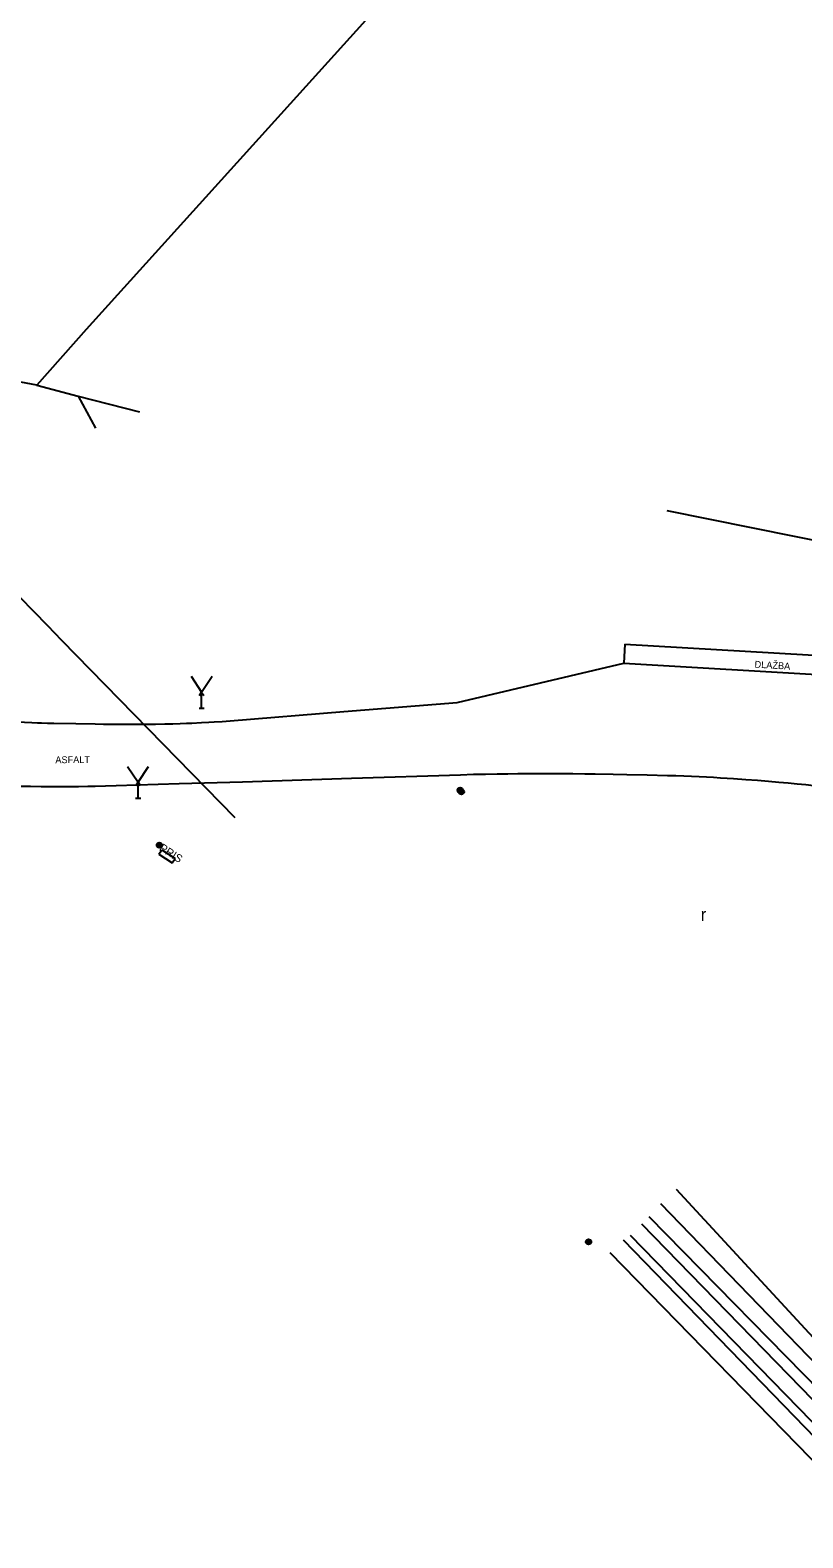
# Model space of a CAD drawing. Extents: x -540235 to -537963, y -1184915 to -1183660.
# Drawn here: x -538311.8 to -538238.6, y -1183987.5 to -1183844.8 of the extents above; entities that cross this region are included whole.
import ezdxf

# ---------------------------------------------------------------- set-up
doc = ezdxf.new("R2010")
doc.units = 0
for name, color, linetype in [('Vrstva 10', 7, 'Continuous'), ('Vrstva 11', 7, 'Continuous'), ('Vrstva 12', 7, 'Continuous'), ('Vrstva 13', 7, 'Continuous'), ('Vrstva 14', 7, 'Continuous'), ('Vrstva 24', 7, 'Continuous'), ('Vrstva 25', 7, 'Continuous'), ('Vrstva 36', 7, 'Continuous'), ('Vrstva 40', 7, 'Continuous'), ('Vrstva 41', 7, 'Continuous'), ('Vrstva 7', 7, 'Continuous')]:
    doc.layers.add(name, color=color, linetype=linetype)

msp = doc.modelspace()

# ---------------------------------------------------------------- linework, layer by layer
at = {"layer": 'Vrstva 10'}
for p, q in [((-538271.38, -1183908.42), (-538255.61, -1183904.7)), ((-538255.61, -1183904.7), (-538235.7, -1183905.88)), ((-538282.12, -1183909.285), (-538271.38, -1183908.42)), ((-538292.86, -1183910.15), (-538282.12, -1183909.285)), ((-538291.71, -1183915.91), (-538281.38, -1183915.58)), ((-538281.38, -1183915.58), (-538271.05, -1183915.25)), ((-538306.337, -1183916.342), (-538305.668, -1183916.331)), ((-538303.66, -1183916.28), (-538297.685, -1183916.096)), ((-538297.685, -1183916.096), (-538291.71, -1183915.91))]:
    msp.add_line(p, q, dxfattribs=at)
for points in [[(-538318.057, -1183909.725), (-538317.529, -1183909.794), (-538317.034, -1183909.855), (-538316.569, -1183909.909), (-538316.134, -1183909.958), (-538315.725, -1183910.001), (-538314.958, -1183910.076), (-538314.287, -1183910.135), (-538313.699, -1183910.182), (-538313.184, -1183910.219), (-538312.733, -1183910.249), (-538312.339, -1183910.273), (-538311.647, -1183910.309), (-538311.129, -1183910.332), (-538310.739, -1183910.347), (-538310.155, -1183910.366), (-538309.57, -1183910.38)], [(-538309.57, -1183910.38), (-538307.481, -1183910.421), (-538305.652, -1183910.45), (-538304.852, -1183910.461), (-538304.102, -1183910.469), (-538303.398, -1183910.474), (-538302.739, -1183910.477), (-538302.12, -1183910.477), (-538300.961, -1183910.473), (-538299.947, -1183910.463)], [(-538299.947, -1183910.463), (-538299.06, -1183910.448), (-538298.284, -1183910.43), (-538297.605, -1183910.41)], [(-538297.605, -1183910.41), (-538297.011, -1183910.39), (-538296.492, -1183910.369), (-538295.583, -1183910.327), (-538294.902, -1183910.29), (-538294.391, -1183910.26), (-538293.625, -1183910.208), (-538292.86, -1183910.15)], [(-538271.05, -1183915.25), (-538269.826, -1183915.215), (-538268.679, -1183915.188), (-538267.603, -1183915.169), (-538266.594, -1183915.155), (-538265.648, -1183915.146), (-538264.762, -1183915.14)], [(-538264.762, -1183915.14), (-538263.93, -1183915.137), (-538263.151, -1183915.137), (-538261.689, -1183915.142), (-538260.411, -1183915.151), (-538259.292, -1183915.163), (-538258.313, -1183915.176), (-538256.599, -1183915.204), (-538255.314, -1183915.229)], [(-538255.314, -1183915.229), (-538253.387, -1183915.272), (-538251.46, -1183915.32), (-538250.674, -1183915.342), (-538249.913, -1183915.368), (-538249.177, -1183915.397), (-538248.463, -1183915.428), (-538247.772, -1183915.461), (-538247.103, -1183915.496), (-538246.454, -1183915.533), (-538245.827, -1183915.571)], [(-538245.827, -1183915.571), (-538245.219, -1183915.61), (-538244.041, -1183915.692)], [(-538244.041, -1183915.692), (-538242.938, -1183915.775), (-538241.904, -1183915.86), (-538240.934, -1183915.944), (-538240.026, -1183916.027), (-538239.175, -1183916.109), (-538238.377, -1183916.189), (-538237.629, -1183916.267), (-538236.928, -1183916.342), (-538235.613, -1183916.488), (-538234.464, -1183916.622)], [(-538315.674, -1183916.253), (-538314.923, -1183916.278), (-538314.219, -1183916.298), (-538313.559, -1183916.314), (-538312.941, -1183916.328), (-538311.78, -1183916.347), (-538310.765, -1183916.359), (-538309.877, -1183916.364), (-538309.1, -1183916.365), (-538308.419, -1183916.363), (-538307.229, -1183916.354), (-538306.337, -1183916.342)], [(-538305.668, -1183916.331), (-538304.664, -1183916.308), (-538303.66, -1183916.28)]]:
    msp.add_lwpolyline(points, dxfattribs=at)
at = {"layer": 'Vrstva 11'}
for q in [(-538255.61, -1183904.7), (-538235.44, -1183904.08)]:
    msp.add_line((-538255.503, -1183902.89), q, dxfattribs=at)
at = {"layer": 'Vrstva 12'}
for p, q in [((-538295.57, -1183908.94), (-538295.57, -1183907.44)), ((-538295.82, -1183908.94), (-538295.32, -1183908.94)), ((-538301.59, -1183917.46), (-538301.59, -1183915.96)), ((-538301.84, -1183917.46), (-538301.34, -1183917.46)), ((-538253.91, -1183957.76), (-538227.69, -1183984.7)), ((-538254.99, -1183958.81), (-538228.77, -1183985.73))]:
    msp.add_line(p, q, dxfattribs=at)
for points in [[(-538296.57, -1183905.94), (-538295.57, -1183907.44), (-538294.57, -1183905.94)], [(-538295.763, -1183907.745), (-538295.57, -1183907.44), (-538295.377, -1183907.745)], [(-538302.59, -1183914.46), (-538301.59, -1183915.96), (-538300.59, -1183914.46)], [(-538301.783, -1183916.265), (-538301.59, -1183915.96), (-538301.397, -1183916.265)]]:
    msp.add_lwpolyline(points, dxfattribs=at)
at = {"layer": 'Vrstva 13'}
for p, q in [((-538300.605, -1183910.945), (-538308.8, -1183902.55)), ((-538292.41, -1183919.34), (-538300.605, -1183910.945))]:
    msp.add_line(p, q, dxfattribs=at)
msp.add_lwpolyline([(-538308.8, -1183902.55), (-538310.141, -1183901.174), (-538311.458, -1183899.817), (-538312.752, -1183898.478), (-538314.023, -1183897.158), (-538315.271, -1183895.856)], dxfattribs=at)
at = {"layer": 'Vrstva 14'}
for p, q in [((-538250.65, -1183954.48), (-538224.97, -1183982.24)), ((-538253.23, -1183957.04), (-538226.86, -1183983.95)), ((-538252.11, -1183955.81), (-538225.77, -1183983.08)), ((-538229.39, -1183986.35), (-538255.63, -1183959.29)), ((-538230.59, -1183987.46), (-538256.89, -1183960.49))]:
    msp.add_line(p, q, dxfattribs=at)
at = {"layer": 'Vrstva 24'}
for p, q in [((-538299.612, -1183922.769), (-538299.34, -1183922.35)), ((-538299.612, -1183922.769), (-538298.352, -1183923.589)), ((-538299.34, -1183922.35), (-538298.08, -1183923.17)), ((-538298.352, -1183923.589), (-538298.08, -1183923.17))]:
    msp.add_line(p, q, dxfattribs=at)
at = {"layer": 'Vrstva 25'}
for centre, radius in [((-538271.09, -1183916.72), 0.25), ((-538271.09, -1183916.72), 0.2), ((-538271.09, -1183916.72), 0.15), ((-538270.97, -1183916.86), 0.25), ((-538271.09, -1183916.72), 0.1), ((-538270.97, -1183916.86), 0.2), ((-538271.09, -1183916.72), 0.05), ((-538270.97, -1183916.86), 0.15), ((-538270.97, -1183916.86), 0.1), ((-538270.97, -1183916.86), 0.05), ((-538299.58, -1183921.92), 0.25), ((-538299.58, -1183921.92), 0.2), ((-538299.58, -1183921.92), 0.15), ((-538299.58, -1183921.92), 0.1), ((-538299.58, -1183921.92), 0.05), ((-538258.93, -1183959.45), 0.25), ((-538258.93, -1183959.45), 0.2), ((-538258.93, -1183959.45), 0.15), ((-538258.93, -1183959.45), 0.1), ((-538258.93, -1183959.45), 0.05)]:
    msp.add_circle(centre, radius, dxfattribs=at)
at = {"layer": 'Vrstva 7'}
for p, q in [((-538216.1, -1183773.14), (-538306.52, -1183873.14)), ((-538306.52, -1183873.14), (-538311.19, -1183878.4)), ((-538311.19, -1183878.4), (-538313.7, -1183877.93)), ((-538307.27, -1183879.42), (-538305.63, -1183882.45)), ((-538251.53, -1183890.24), (-538212.179, -1183898.167))]:
    msp.add_line(p, q, dxfattribs=at)
msp.add_lwpolyline([(-538311.19, -1183878.4), (-538307.27, -1183879.42), (-538301.462, -1183880.931)], dxfattribs=at)

# ---------------------------------------------------------------- texts
at = {"layer": 'Vrstva 36'}
msp.add_text('r', height=1.2, dxfattribs=at).set_placement((-538248.318, -1183929.08))
at = {"layer": 'Vrstva 40'}
for s, rotation, p in [('DLAŽBA', 356.608236, (-538243.232, -1183905.117)), ('ASFALT', 0.249103, (-538309.423, -1183914.164))]:
    msp.add_text(s, height=0.65, rotation=rotation, dxfattribs=at).set_placement(p)
at = {"layer": 'Vrstva 41'}
msp.add_text('PRIS', height=0.75, rotation=326.944178, dxfattribs=at).set_placement((-538299.653, -1183922.356))

doc.saveas('drawing.dxf')
